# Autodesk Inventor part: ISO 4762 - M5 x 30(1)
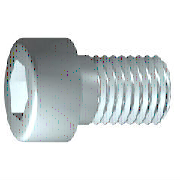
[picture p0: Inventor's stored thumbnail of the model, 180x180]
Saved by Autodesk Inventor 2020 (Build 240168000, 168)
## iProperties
Created: 2019-01
Part Number: ISO 4762 - M5 x 30(1)
Material: Nerezová ocel 440C
Description: Šroub s válcovou hlavou s vnitřním šestihranem
Document SubType Name: Modeling
Standard: ISO 4762
Designer: doma
Standard Revision: Fourth edition 2004-03-01
Standards Organization: ISO
Language: cs-CZ
Size Designation: M5 x 30
Categories: <MemberInstance><Categories><Category DisplayName="Spojovací materiál" InternalName="e4da775c-781d-43d5-af7c-5136215cf5a6" Mnemonic="FSTN"><Category DisplayName
Density: 7.75 g/cm^3
Appearance: Pololeštěná
IsCustomPart: 0
Author: doma
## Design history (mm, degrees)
sketch "Náčrt1"
  geometry: L1 (-1.167, 0)-(30, 0); L2 (30, 0)-(30, 2.5); L3 (30, 2.5)-(8, 2.5); L4 (8, 2.5)-(7.509, 2.5); L5 (7.509, 2.5)-(0, 2.5); L6 (0, 2.5)-(0, 4.25); L7 (0, 4.25)-(-5, 4.25); L8 (-5, 4.25)-(-5, 2.309); L9 (-5, 2.309)-(-2.5, 2.309); L10 (-2.5, 2.309)-(-1.167, 0); L11 (-12, 0)-(37, 0) reference; L12 (0, -0.85)-(0, 5.1) reference; L13 (8, 2.5)-(0, 2.5)
  constraints: 22 end point, 6 parallel, 2 collinear, 2 perpendicular, 1 horizontal, 1 point on line
  dimensions: "d1" = 22 distance from line of L3.end L2 (= GEL); "d2" = 0.49086 distance of L4.end L3.end (computed from GAL); "d3" = 5 distance between parallel lines of L8 L6 (= KOH); "d4" = 2.5 distance of L8.end L9.end (= INTI); "d5" = 60 deg angle of L10 L1; "d6" = 5 diameter of L3 L1 (= GD); "d7" = 5 diameter of L5 L1 (= BDM); "d8" = 4.6188 diameter of L9 L1 (= 1.1547 x SW); "d9" = 8.5 diameter of L7 L1 (= KOD); "d26" = 30 distance between parallel lines of L12 L2 (= NLG)
revolve "Těleso" sketch "Náčrt1" stored, may be unused: angle "d10" = 90 deg
sketch "Náčrt2"
  geometry: L1 (0, -5.95)-(0, 5.95) reference; L2 (-5.95, 0)-(5.95, 0) reference; L3 (2.309, 0)-(1.155, -2); L4 (1.155, -2)-(-1.155, -2); L5 (-1.155, -2)-(-2.309, 0); L6 (-2.309, 0)-(-1.155, 2); L7 (-1.155, 2)-(1.155, 2); L8 (1.155, 2)-(2.309, 0); 2 further points
  constraints: 12 end point, 1 coincident, 1 horizontal alignment, 1 point on line, 12 other
extrude "Drážka" join sketch "Náčrt2" stored distance "d11" = 10; taper "d12" = 0 deg
workplane "Work Plane1"
fillet "Fillet2" dims "d30" = 0.1 (= R)
body "Solid1"
fillet "Zaoblení1" dims "d17" = 0.5 (= RR)
feature "Závit" dims "d13" = 22 (= GEL), "d14" = 0
chamfer "Zkosení1" distance "d15" = 0.49076 (= -0.5 x SPD + 0.5 x GD); stored, may be unused: second distance "d16" = 0.49076 (= GUL), angle "d27" = 45 deg
other parameters: "GD" = 5 [user parameter; used in 2 equation terms], "NLG" = 30 [user parameter; used in 1 equation term], "GEL" = 22 [user parameter; used in 2 equation terms], "KOD" = 8.5 [user parameter; used in 1 equation term], "KOH" = 5 [user parameter; used in 1 equation term], "INTI" = 2.5 [user parameter; used in 1 equation term], "GAL" = 0.49076 (= 0.61345 x PTC) [user parameter; used in 1 equation term], "GUL" = 0.49076 (= 0.61345 x PTC) [user parameter; used in 1 equation term], "BDM" = 5 (= NND) [user parameter; used in 1 equation term], "SW" = 4 [user parameter; used in 2 equation terms], "RR" = 0.5 [user parameter; used in 1 equation term], "SPD" = 4.01848 (= NND - 1.2269 x PTC) [user parameter; used in 1 equation term], "d19" = 0, "d28" = 0, "d29" = 0, "R" = 0.1 [user parameter; used in 1 equation term], "TOA" = 30 deg [user parameter], "GD1" = 4.01848 (= THREADDIA - 1.2269 x PTC) [user parameter], "THREADDIA" = 5 [user parameter; used in 1 equation term], "FAWI" = 45 deg [user parameter], "TPU" = 12.5 (computed from PTC) [user parameter], "PTC" = 0.8 [user parameter; used in 5 equation terms], "NND" = 5 [user parameter; used in 2 equation terms], "E0" = 4.62 (= 1.155 x SW) [user parameter]
